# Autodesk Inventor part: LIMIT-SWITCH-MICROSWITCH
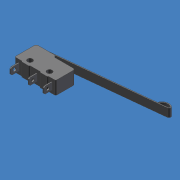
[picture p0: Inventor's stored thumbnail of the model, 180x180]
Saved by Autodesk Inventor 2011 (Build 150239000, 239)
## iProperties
Created: 2007-08
Part Number: LIMIT-SWITCH-MICROSWITCH
Document SubType Name: Modeling
Density: 1 g/cm^3
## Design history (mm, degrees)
feature "Base1"
workplane "Work Plane1"
body "Solid1"
